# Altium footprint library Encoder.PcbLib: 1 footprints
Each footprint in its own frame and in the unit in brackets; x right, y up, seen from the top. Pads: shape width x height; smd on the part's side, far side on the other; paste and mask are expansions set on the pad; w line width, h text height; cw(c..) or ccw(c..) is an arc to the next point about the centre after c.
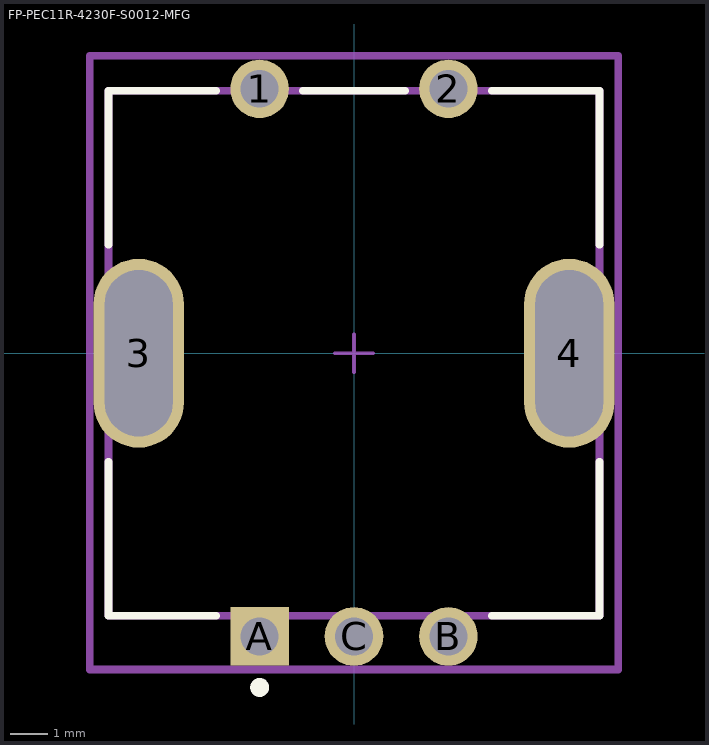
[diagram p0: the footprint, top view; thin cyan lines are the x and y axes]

## FP-PEC11R-4230F-S0012-MFG [mm]
pads (7):
  round 1.55 hole 1 paste-2539.97 mask+0: 1(-2.5,7) 2(2.5,7) B(2.5,-7.5) C(0,-7.5)
  rrect100% 2.4x5 hole 4.4 slot 1.8 at 0 deg paste-2539.97 mask+0: 3(-5.7,0) 4(5.7,0)
  rect 1.55x1.55 hole 1 paste-2539.97 mask+0: A(-2.5,-7.5)
Top Overlay:
  circle w0.25: c-2.5,-8.85 r0.125
  lines w0.2: -6.5,-2.875 -6.5,-6.95 -3.65,-6.95 ; -6.5,2.875 -6.5,6.95 -3.65,6.95 ; -1.35,6.95 1.35,6.95 ; 3.65,-6.95 6.5,-6.95 6.5,-2.875 ; 3.65,6.95 6.5,6.95 6.5,2.875
Top Assembly:
  lines w0.2: -7,-8.375 -7,7.875 7,7.875 7,-8.375 -7,-8.375
  text ".Designator" at 0,-0.062 h1
Top 3D Body:
  lines w0.2: -6.5,-6.95 -6.5,6.95 6.5,6.95 6.5,-6.95 -6.5,-6.95
Top Courtyard:
  lines w0.2: -7,-8.375 -7,7.875 7,7.875 7,-8.375 -7,-8.375
Top Component Center:
  lines w0.1: -0.5,0 0.5,0 ; 0,-0.5 0,0.5
3D body "Enc_Bourns_PEC11R-4230F-S0012_eec.STEP": height 0.25, standoff 0, extent -7,-8.375 7,7.875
